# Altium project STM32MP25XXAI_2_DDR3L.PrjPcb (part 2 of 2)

## Sheet 2_DDR3L_16bits.SchDoc: 2_DDR3L_16bits
size A3; Date: Not used; ApprovedBy: Not used; CheckedBy: Not used; Author: Not used; CompanyName: STMicroelectronics; DrawnBy: Not used; Engineer: Not used; Organization: Not used; Address1: Not used; Address2: Not used; Address3: Not used; Address4: Not used; DocumentNumber: 6; Revision: Not used; SheetNumber: 6; SheetTotal: 7
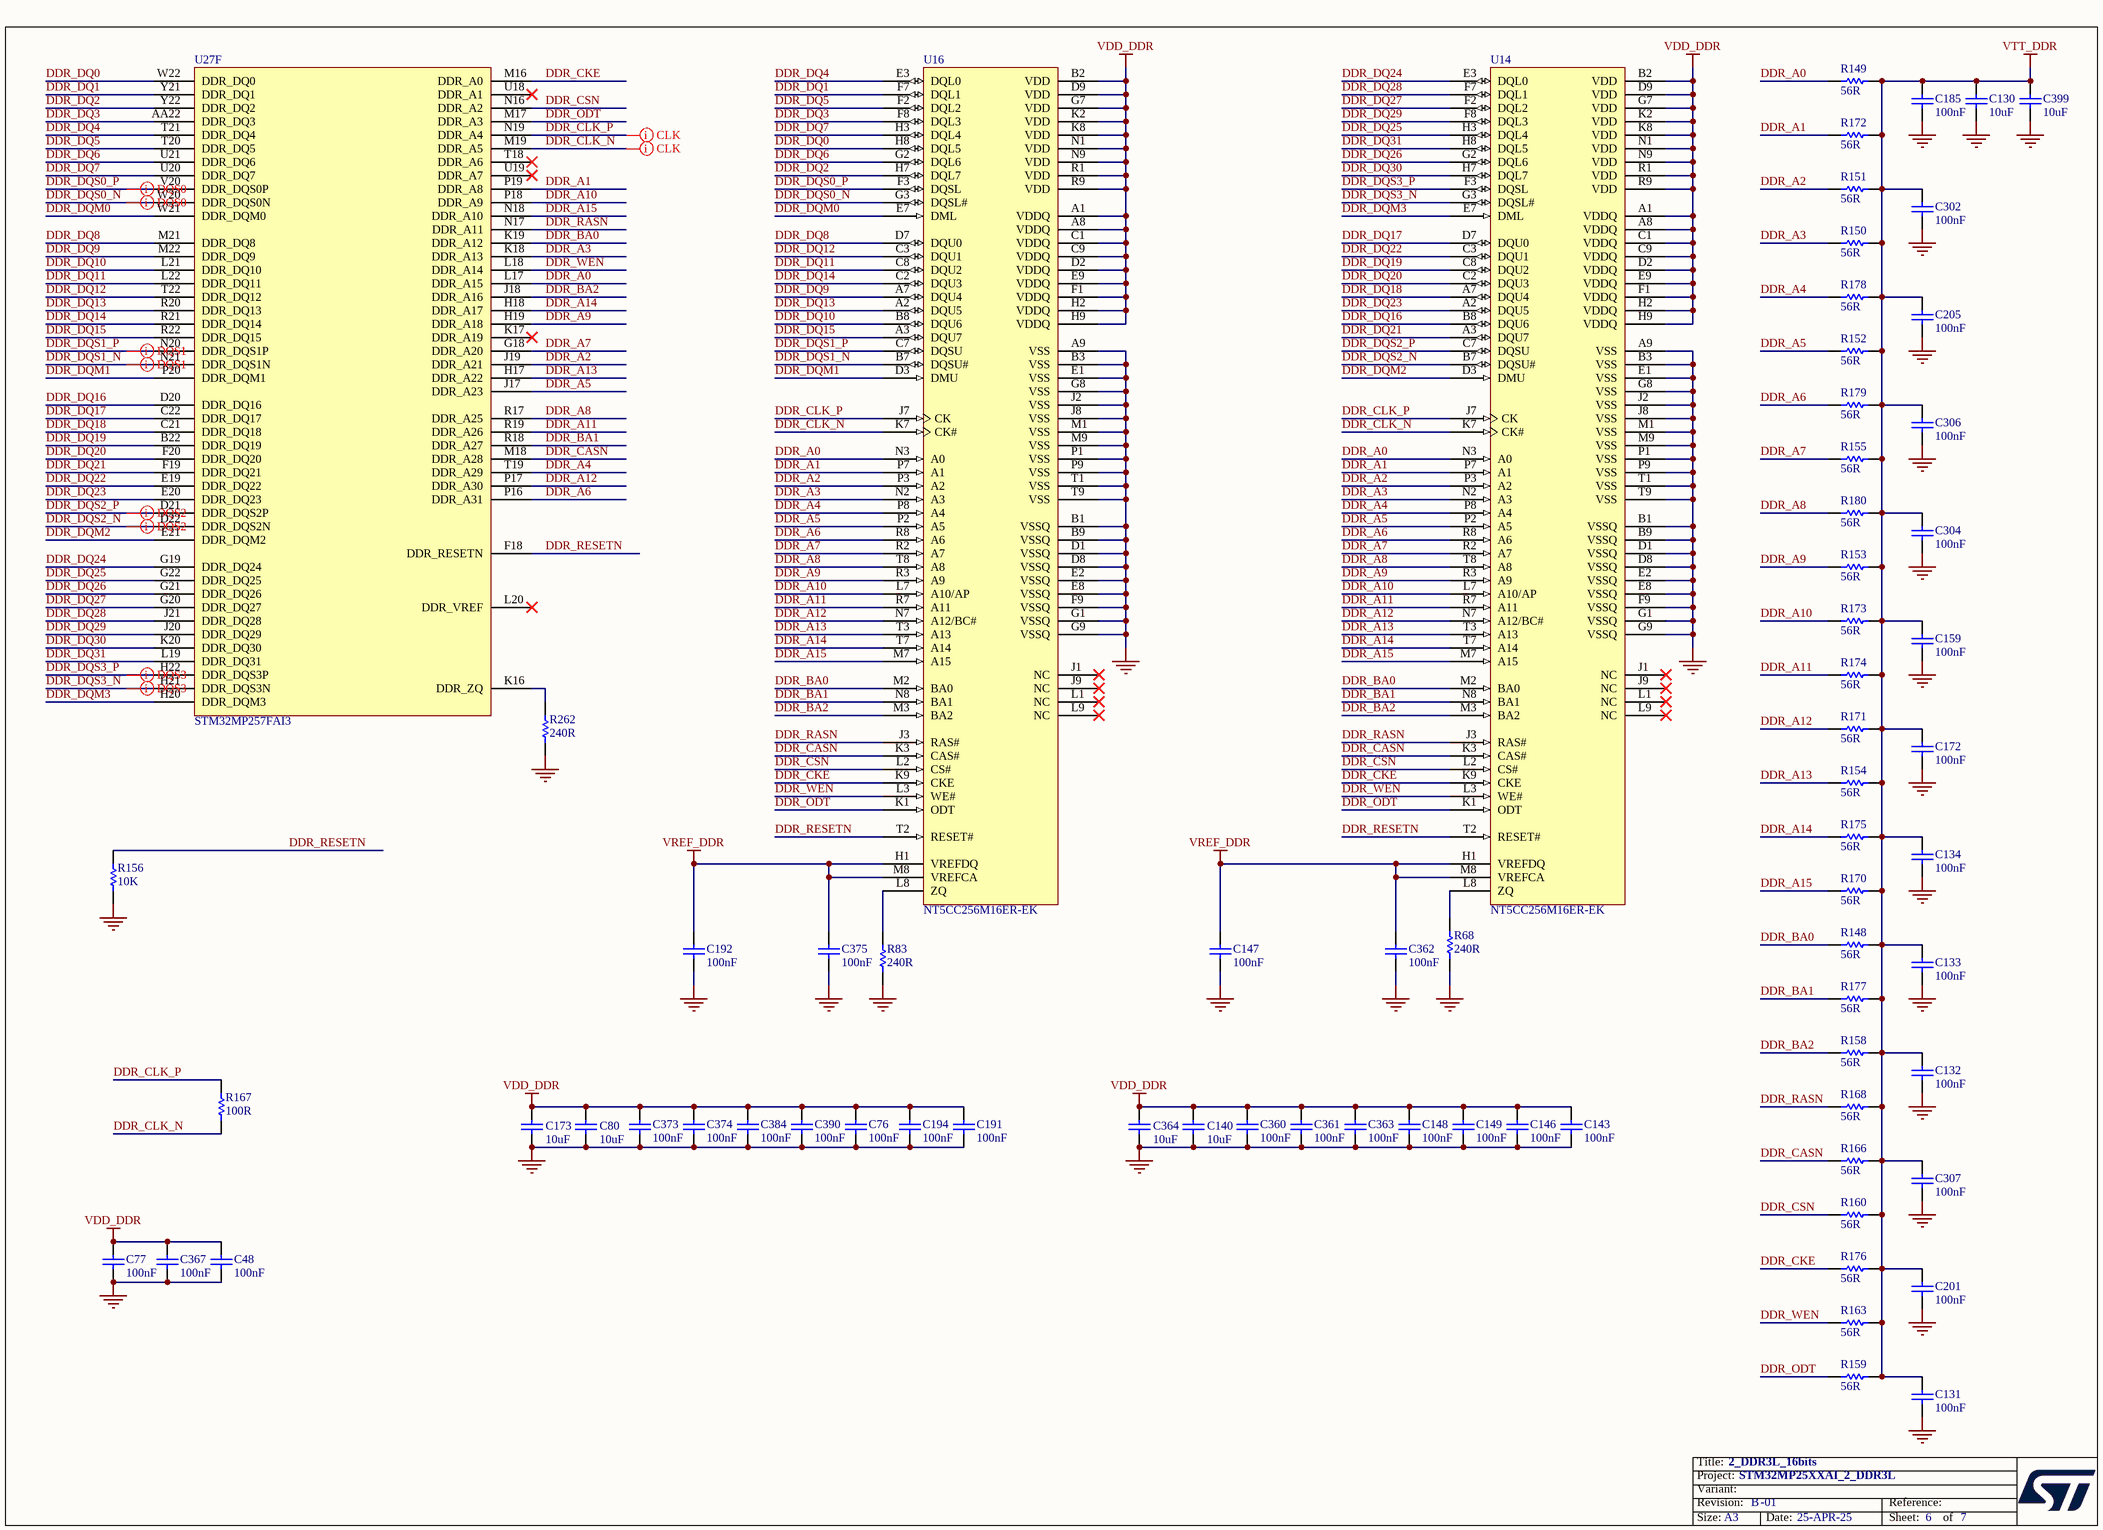
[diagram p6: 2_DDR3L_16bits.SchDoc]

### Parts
C48  value 100nF  [C0402]  (hidden comment: Capacitor)
C76  value 100nF  [C0402]  (hidden comment: Capacitor)
C77  value 100nF  [C0402]  (hidden comment: Capacitor)
C80  value 10uF  [C0603]  (hidden comment: Capacitor)
C130  value 10uF  [C0603]  (hidden comment: Capacitor)
C131  value 100nF  [C0402]  (hidden comment: Capacitor)
C132  value 100nF  [C0402]  (hidden comment: Capacitor)
C133  value 100nF  [C0402]  (hidden comment: Capacitor)
C134  value 100nF  [C0402]  (hidden comment: Capacitor)
C140  value 10uF  [C0603]  (hidden comment: Capacitor)
C143  value 100nF  [C0402]  (hidden comment: Capacitor)
C146  value 100nF  [C0402]  (hidden comment: Capacitor)
C147  value 100nF  [C0402]  (hidden comment: Capacitor)
C148  value 100nF  [C0402]  (hidden comment: Capacitor)
C149  value 100nF  [C0402]  (hidden comment: Capacitor)
C159  value 100nF  [C0402]  (hidden comment: Capacitor)
C172  value 100nF  [C0402]  (hidden comment: Capacitor)
C173  value 10uF  [C0603]  (hidden comment: Capacitor)
C185  value 100nF  [C0402]  (hidden comment: Capacitor)
C191  value 100nF  [C0402]  (hidden comment: Capacitor)
C192  value 100nF  [C0402]  (hidden comment: Capacitor)
C194  value 100nF  [C0402]  (hidden comment: Capacitor)
C201  value 100nF  [C0402]  (hidden comment: Capacitor)
C205  value 100nF  [C0402]  (hidden comment: Capacitor)
C302  value 100nF  [C0402]  (hidden comment: Capacitor)
C304  value 100nF  [C0402]  (hidden comment: Capacitor)
C306  value 100nF  [C0402]  (hidden comment: Capacitor)
C307  value 100nF  [C0402]  (hidden comment: Capacitor)
C360  value 100nF  [C0402]  (hidden comment: Capacitor)
C361  value 100nF  [C0402]  (hidden comment: Capacitor)
C362  value 100nF  [C0402]  (hidden comment: Capacitor)
C363  value 100nF  [C0402]  (hidden comment: Capacitor)
C364  value 10uF  [C0603]  (hidden comment: Capacitor)
C367  value 100nF  [C0402]  (hidden comment: Capacitor)
C373  value 100nF  [C0402]  (hidden comment: Capacitor)
C374  value 100nF  [C0402]  (hidden comment: Capacitor)
C375  value 100nF  [C0402]  (hidden comment: Capacitor)
C384  value 100nF  [C0402]  (hidden comment: Capacitor)
C390  value 100nF  [C0402]  (hidden comment: Capacitor)
C399  value 10uF  [C0603]  (hidden comment: Capacitor)
R68  value 240R  [R0402]  (hidden comment: Resistor)
R83  value 240R  [R0402]  (hidden comment: Resistor)
R148  value 56R  [R0402]  (hidden comment: Resistor)
R149  value 56R  [R0402]  (hidden comment: Resistor)
R150  value 56R  [R0402]  (hidden comment: Resistor)
R151  value 56R  [R0402]  (hidden comment: Resistor)
R152  value 56R  [R0402]  (hidden comment: Resistor)
R153  value 56R  [R0402]  (hidden comment: Resistor)
R154  value 56R  [R0402]  (hidden comment: Resistor)
R155  value 56R  [R0402]  (hidden comment: Resistor)
R156  value 10K  [R0402]  (hidden comment: Resistor)
R158  value 56R  [R0402]  (hidden comment: Resistor)
R159  value 56R  [R0402]  (hidden comment: Resistor)
R160  value 56R  [R0402]  (hidden comment: Resistor)
R163  value 56R  [R0402]  (hidden comment: Resistor)
R166  value 56R  [R0402]  (hidden comment: Resistor)
R167  value 100R  [R0402]  (hidden comment: Resistor)
R168  value 56R  [R0402]  (hidden comment: Resistor)
R170  value 56R  [R0402]  (hidden comment: Resistor)
R171  value 56R  [R0402]  (hidden comment: Resistor)
R172  value 56R  [R0402]  (hidden comment: Resistor)
R173  value 56R  [R0402]  (hidden comment: Resistor)
R174  value 56R  [R0402]  (hidden comment: Resistor)
R175  value 56R  [R0402]  (hidden comment: Resistor)
R176  value 56R  [R0402]  (hidden comment: Resistor)
R177  value 56R  [R0402]  (hidden comment: Resistor)
R178  value 56R  [R0402]  (hidden comment: Resistor)
R179  value 56R  [R0402]  (hidden comment: Resistor)
R180  value 56R  [R0402]  (hidden comment: Resistor)
R262  value 240R  [R0201_H0P23]  (hidden comment: Resistor)
U14  NT5CC256M16ER-EK  [ICC_VFBGA96_9x13_P080]
U16  NT5CC256M16ER-EK  [ICC_VFBGA96_9x13_P080]
U27  STM32MP257FAI3  [ICC_LFBGA436_18X18_P080_H1P70_STM32MP257_CODE-B0D1]  (part F of 9)

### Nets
GND: C48.1 C76.1 C77.1 C80.1 C130.1 C131.1 C132.1 C133.1 C134.1 C140.1 C143.1 C146.1 C147.1 C148.1 C149.1 C159.1 C172.1 C173.1 C185.1 C191.1 C192.1 C194.1 C201.1 C205.1 C302.1 C304.1 C306.1 C307.1 C360.1 C361.1 C362.1 C363.1 C364.1 C367.1 C373.1 C374.1 C375.1 C384.1 C390.1 C399.1 R68.1 R83.1 R156.1 R262.1 U14.A9(VSS) U14.B1(VSSQ) U14.B3(VSS) U14.B9(VSSQ) U14.D1(VSSQ) U14.D8(VSSQ) U14.E1(VSS) U14.E2(VSSQ) U14.E8(VSSQ) U14.F9(VSSQ) U14.G1(VSSQ) U14.G8(VSS) U14.G9(VSSQ) U14.J2(VSS) U14.J8(VSS) U14.M1(VSS) U14.M9(VSS) U14.P1(VSS) U14.P9(VSS) U14.T1(VSS) U14.T9(VSS) U16.A9(VSS) U16.B1(VSSQ) U16.B3(VSS) U16.B9(VSSQ) U16.D1(VSSQ) U16.D8(VSSQ) U16.E1(VSS) U16.E2(VSSQ) U16.E8(VSSQ) U16.F9(VSSQ) U16.G1(VSSQ) U16.G8(VSS) U16.G9(VSSQ) U16.J2(VSS) U16.J8(VSS) U16.M1(VSS) U16.M9(VSS) U16.P1(VSS) U16.P9(VSS) U16.T1(VSS) U16.T9(VSS)
VDD_DDR: C48.2 C76.2 C77.2 C80.2 C140.2 C143.2 C146.2 C148.2 C149.2 C173.2 C191.2 C194.2 C360.2 C361.2 C363.2 C364.2 C367.2 C373.2 C374.2 C384.2 C390.2 U14.A1(VDDQ) U14.A8(VDDQ) U14.B2(VDD) U14.C1(VDDQ) U14.C9(VDDQ) U14.D2(VDDQ) U14.D9(VDD) U14.E9(VDDQ) U14.F1(VDDQ) U14.G7(VDD) U14.H2(VDDQ) U14.H9(VDDQ) U14.K2(VDD) U14.K8(VDD) U14.N1(VDD) U14.N9(VDD) U14.R1(VDD) U14.R9(VDD) U16.A1(VDDQ) U16.A8(VDDQ) U16.B2(VDD) U16.C1(VDDQ) U16.C9(VDDQ) U16.D2(VDDQ) U16.D9(VDD) U16.E9(VDDQ) U16.F1(VDDQ) U16.G7(VDD) U16.H2(VDDQ) U16.H9(VDDQ) U16.K2(VDD) U16.K8(VDD) U16.N1(VDD) U16.N9(VDD) U16.R1(VDD) U16.R9(VDD)
VREF_DDR: C147.2 C192.2 C362.2 C375.2 U14.H1(VREFDQ) U14.M8(VREFCA) U16.H1(VREFDQ) U16.M8(VREFCA)
VTT_DDR: C130.2 C131.2 C132.2 C133.2 C134.2 C159.2 C172.2 C185.2 C201.2 C205.2 C302.2 C304.2 C306.2 C307.2 C399.2 R148.2 R149.2 R150.2 R151.2 R152.2 R153.2 R154.2 R155.2 R158.2 R159.2 R160.2 R163.2 R166.2 R168.2 R170.2 R171.2 R172.2 R173.2 R174.2 R175.2 R176.2 R177.2 R178.2 R179.2 R180.2
DDR_A0: R149.1 U14.N3(A0) U16.N3(A0) U27.L17(DDR_A15)
DDR_A1: R172.1 U14.P7(A1) U16.P7(A1) U27.P19(DDR_A8)
DDR_A2: R151.1 U14.P3(A2) U16.P3(A2) U27.J19(DDR_A21)
DDR_A3: R150.1 U14.N2(A3) U16.N2(A3) U27.K18(DDR_A13)
DDR_A4: R178.1 U14.P8(A4) U16.P8(A4) U27.T19(DDR_A29)
DDR_A5: R152.1 U14.P2(A5) U16.P2(A5) U27.J17(DDR_A23)
DDR_A6: R179.1 U14.R8(A6) U16.R8(A6) U27.P16(DDR_A31)
DDR_A7: R155.1 U14.R2(A7) U16.R2(A7) U27.G18(DDR_A20)
DDR_A8: R180.1 U14.T8(A8) U16.T8(A8) U27.R17(DDR_A25)
DDR_A9: R153.1 U14.R3(A9) U16.R3(A9) U27.H19(DDR_A18)
DDR_A10: R173.1 U14.L7(A10/AP) U16.L7(A10/AP) U27.P18(DDR_A9)
DDR_A11: R174.1 U14.R7(A11) U16.R7(A11) U27.R19(DDR_A26)
DDR_A12: R171.1 U14.N7(A12/BC#) U16.N7(A12/BC#) U27.P17(DDR_A30)
DDR_A13: R154.1 U14.T3(A13) U16.T3(A13) U27.H17(DDR_A22)
DDR_A14: R175.1 U14.T7(A14) U16.T7(A14) U27.H18(DDR_A17)
DDR_A15: R170.1 U14.M7(A15) U16.M7(A15) U27.N18(DDR_A10)
DDR_BA0: R148.1 U14.M2(BA0) U16.M2(BA0) U27.K19(DDR_A12)
DDR_BA1: R177.1 U14.N8(BA1) U16.N8(BA1) U27.R18(DDR_A27)
DDR_BA2: R158.1 U14.M3(BA2) U16.M3(BA2) U27.J18(DDR_A16)
DDR_CASN: R166.1 U14.K3(CAS#) U16.K3(CAS#) U27.M18(DDR_A28)
DDR_CKE: R176.1 U14.K9(CKE) U16.K9(CKE) U27.M16(DDR_A0)
DDR_CLK_N: R167.2 U14.K7(CK#) U16.K7(CK#) U27.M19(DDR_A5)
DDR_CLK_P: R167.1 U14.J7(CK) U16.J7(CK) U27.N19(DDR_A4)
DDR_CSN: R160.1 U14.L2(CS#) U16.L2(CS#) U27.N16(DDR_A2)
DDR_DQ0: U16.H8(DQL5) U27.W22(DDR_DQ0)
DDR_DQ1: U16.F7(DQL1) U27.Y21(DDR_DQ1)
DDR_DQ2: U16.H7(DQL7) U27.Y22(DDR_DQ2)
DDR_DQ3: U16.F8(DQL3) U27.AA22(DDR_DQ3)
DDR_DQ4: U16.E3(DQL0) U27.T21(DDR_DQ4)
DDR_DQ5: U16.F2(DQL2) U27.T20(DDR_DQ5)
DDR_DQ6: U16.G2(DQL6) U27.U21(DDR_DQ6)
DDR_DQ7: U16.H3(DQL4) U27.U20(DDR_DQ7)
DDR_DQ8: U16.D7(DQU0) U27.M21(DDR_DQ8)
DDR_DQ9: U16.A7(DQU4) U27.M22(DDR_DQ9)
DDR_DQ10: U16.B8(DQU6) U27.L21(DDR_DQ10)
DDR_DQ11: U16.C8(DQU2) U27.L22(DDR_DQ11)
DDR_DQ12: U16.C3(DQU1) U27.T22(DDR_DQ12)
DDR_DQ13: U16.A2(DQU5) U27.R20(DDR_DQ13)
DDR_DQ14: U16.C2(DQU3) U27.R21(DDR_DQ14)
DDR_DQ15: U16.A3(DQU7) U27.R22(DDR_DQ15)
DDR_DQ16: U14.B8(DQU6) U27.D20(DDR_DQ16)
DDR_DQ17: U14.D7(DQU0) U27.C22(DDR_DQ17)
DDR_DQ18: U14.A7(DQU4) U27.C21(DDR_DQ18)
DDR_DQ19: U14.C8(DQU2) U27.B22(DDR_DQ19)
DDR_DQ20: U14.C2(DQU3) U27.F20(DDR_DQ20)
DDR_DQ21: U14.A3(DQU7) U27.F19(DDR_DQ21)
DDR_DQ22: U14.C3(DQU1) U27.E19(DDR_DQ22)
DDR_DQ23: U14.A2(DQU5) U27.E20(DDR_DQ23)
DDR_DQ24: U14.E3(DQL0) U27.G19(DDR_DQ24)
DDR_DQ25: U14.H3(DQL4) U27.G22(DDR_DQ25)
DDR_DQ26: U14.G2(DQL6) U27.G21(DDR_DQ26)
DDR_DQ27: U14.F2(DQL2) U27.G20(DDR_DQ27)
DDR_DQ28: U14.F7(DQL1) U27.J21(DDR_DQ28)
DDR_DQ29: U14.F8(DQL3) U27.J20(DDR_DQ29)
DDR_DQ30: U14.H7(DQL7) U27.K20(DDR_DQ30)
DDR_DQ31: U14.H8(DQL5) U27.L19(DDR_DQ31)
DDR_DQM0: U16.E7(DML) U27.W21(DDR_DQM0)
DDR_DQM1: U16.D3(DMU) U27.P20(DDR_DQM1)
DDR_DQM2: U14.D3(DMU) U27.E21(DDR_DQM2)
DDR_DQM3: U14.E7(DML) U27.H20(DDR_DQM3)
DDR_DQS0_N: U16.G3(DQSL#) U27.W20(DDR_DQS0N)
DDR_DQS0_P: U16.F3(DQSL) U27.V20(DDR_DQS0P)
DDR_DQS1_N: U16.B7(DQSU#) U27.N21(DDR_DQS1N)
DDR_DQS1_P: U16.C7(DQSU) U27.N20(DDR_DQS1P)
DDR_DQS2_N: U14.B7(DQSU#) U27.D22(DDR_DQS2N)
DDR_DQS2_P: U14.C7(DQSU) U27.D21(DDR_DQS2P)
DDR_DQS3_N: U14.G3(DQSL#) U27.H21(DDR_DQS3N)
DDR_DQS3_P: U14.F3(DQSL) U27.H22(DDR_DQS3P)
DDR_ODT: R159.1 U14.K1(ODT) U16.K1(ODT) U27.M17(DDR_A3)
DDR_RASN: R168.1 U14.J3(RAS#) U16.J3(RAS#) U27.N17(DDR_A11)
DDR_RESETN: R156.2 U14.T2(RESET#) U16.T2(RESET#) U27.F18(DDR_RESETN)
DDR_WEN: R163.1 U14.L3(WE#) U16.L3(WE#) U27.L18(DDR_A14)
NetR68_2: R68.2 U14.L8(ZQ)
NetR83_2: R83.2 U16.L8(ZQ)
NetR262_2: R262.2 U27.K16(DDR_ZQ)

Not connected (* = marked no-connect by the designer): U14 J1(NC)* J9(NC)* L1(NC)* L9(NC)*; U16 J1(NC)* J9(NC)* L1(NC)* L9(NC)*; U27 K17(DDR_A19)* L20(DDR_VREF)* T18(DDR_A6)* U18(DDR_A1)* U19(DDR_A7)*

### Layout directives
differential pair: DDR_CLK_N, DDR_CLK_P, DDR_DQS0_N, DDR_DQS0_P, DDR_DQS1_N, DDR_DQS1_P, DDR_DQS2_N, DDR_DQS2_P, DDR_DQS3_N, DDR_DQS3_P

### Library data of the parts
C48 C76 C77 C131-C134 C143 C146-C149 C159 C172 C185 C191 C192 C194 C201 C205 C302 C304 C306 C307 C360-C363 C367 C373-C375 C384 C390 = MCD-00006: Capacitor, MLCC, 100nF, 16V, X7R, +/-10%, 0402, T=0.5mm; Part_Preference: Recommended; Manufacturer: YAGEO; Manufacturer_Part_Number: CC0402KRX7R7BB104; Alternate_Manufacturer: MURATA; Alternate_Manufacturer_Part_Number: GCM155R71C104KA55D; Partial_Alternate_Internal_Part_Number: MCD-03299; Order_Code_RS: 9402047; Component_Country_Of_Origin: China; ID: 2474; ShowFields: YES
C80 C140 C173 C364 = MCD-00099: Capacitor, MLCC, 10uF, 10V, X5R, +/-10%, 0603, T=0.8mm; Manufacturer_Part_Number: GRM188R61A106KE69D; Manufacturer: MURATA; Part_Preference: Recommended; Partial_Alternate_Internal_Part_Number: MCD-03152; Order_Code_RS: 2494233; Component_Country_Of_Origin: Japan°°; ID: 2770; ShowFields: YES
C130 C399 = MCD-00099: Capacitor, MLCC, 10uF, 10V, X5R, +/-10%, 0603, T=0.8mm; Part_Preference: Recommended; Manufacturer: MURATA; Manufacturer_Part_Number: GRM188R61A106KE69D; Partial_Alternate_Internal_Part_Number: MCD-03152; Order_Code_RS: 2494233; Component_Country_Of_Origin: Japan°°; ShowFields: YES; ID: 2770
R68 R83 = MCD-00120: Resistor,240R,0402,1%,1/16W; Part_Preference: Recommended; Manufacturer: YAGEO; Manufacturer_Part_Number: RC0402FR-07240RL; Component_Country_Of_Origin: China; ID: 2745; ShowFields: YES
R148-R155 R158-R160 R163 R166 R168 R170-R180 = MCD-00054: Resistor, 56R, 0402, +/-1%, 1/16W; Part_Preference: Recommended; Manufacturer: YAGEO; Manufacturer_Part_Number: RC0402FR-0756RL; Order_Code_RS: 9239081; Component_Country_Of_Origin: China; ID: 2538; ShowFields: YES
R156 = MCD-00053: Resistor,10K,0402,1%,1/16W; BMS_Part_Number: 9131590; Part_Preference: Recommended; Manufacturer: YAGEO; Manufacturer_Part_Number: RC0402FR-0710KL; Order_Code_RS: 9239359; Component_Country_Of_Origin: China; ID: 2539; ShowFields: YES
R167 = MCD-01819: Resistor,100R,0402,0,5%,1/16W,±100ppm/°C; Part_Preference: Recommended; Manufacturer: YAGEO; Manufacturer_Part_Number: RC0402DR-07100RL; Component_Country_Of_Origin: China; ID: 3919; ShowFields: YES
R262 = MCD-02253: Resistor,240R,0201,1%,1/20W; Part_Preference: Recommended; Manufacturer: YAGEO; Manufacturer_Part_Number: RC0201FR-07240RL; Component_Country_Of_Origin: China; ID: 4353; ShowFields: YES
U14 U16 = MCD-01811: Memory,DDR3L,4Gb,256Mbx16,933Mhz,1V35,TFBGA; BMS_Part_Number: 9171435; Part_Type: IC; Part_Preference: Recommended; Manufacturer: NANYA; Component_Country_Of_Origin: Taiwan; ID: 3911; ShowFields: YES
U27 = MCD-02000: MPU, ARM Cortex-A35 + M33 32-bit MPU, 808KB RAM, With Crypto; Part_Type: IC; Part_Preference: Recommended; Manufacturer: STMICROELECTRONICS; Manufacturer_HQ_COO: EU; Component_Country_Of_Origin: Unknown; ShowFields: YES; ID: 4100

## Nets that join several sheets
1V8: PMIC (5 pins), STM32MP25XXAI Power (20 pins), eMMC (11 pins)
GND: STM32MP25XXAI I_Os (7 pins), PMIC (62 pins), STM32MP25XXAI Power (104 pins), eMMC (17 pins), 2_DDR3L_16bits (86 pins)
VDD3V3_USB: PMIC (C156.2 U26.13), STM32MP25XXAI Power (R286.1)
VDD_DDR: PMIC (7 pins), STM32MP25XXAI Power (16 pins), 2_DDR3L_16bits (57 pins)
VDD_EMMC: PMIC (C190.1 U26.16), eMMC (6 pins)
VDDA1V8_AON: STM32MP25XXAI I_Os (U27.T7), PMIC (C189.2 U26.14), STM32MP25XXAI Power (C234.2 U27.R7)
VDDCORE: PMIC (6 pins), STM32MP25XXAI Power (20 pins)
VDDCPU: PMIC (5 pins), STM32MP25XXAI Power (14 pins)
VDDGPU: PMIC (6 pins), STM32MP25XXAI Power (12 pins)
VDDIO: STM32MP25XXAI I_Os (R27.2 R260.2 R261.2), PMIC (6 pins), STM32MP25XXAI Power (18 pins)
VDDIO_SDCARD: PMIC (C217.1 U26.2), STM32MP25XXAI Power (C71.2 U27.G10)
VREF_DDR: PMIC (C43.2 U26.45), 2_DDR3L_16bits (8 pins)
VTT_DDR: PMIC (C40.2 U26.44), 2_DDR3L_16bits (40 pins)
eMMC.SDMMC2_CK: STM32MP25XXAI I_Os (U27.A20), eMMC (R49.1 U24.M6)
eMMC.SDMMC2_CMD: STM32MP25XXAI I_Os (U27.F17), eMMC (R37.1 U24.M5)
eMMC.SDMMC2_D0: STM32MP25XXAI I_Os (U27.B19), eMMC (R44.1 U24.A3)
eMMC.SDMMC2_D1: STM32MP25XXAI I_Os (U27.E17), eMMC (U24.A4)
eMMC.SDMMC2_D2: STM32MP25XXAI I_Os (U27.C18), eMMC (U24.A5)
eMMC.SDMMC2_D3: STM32MP25XXAI I_Os (U27.C19), eMMC (U24.B2)
eMMC.SDMMC2_D4: STM32MP25XXAI I_Os (U27.A19), eMMC (U24.B3)
eMMC.SDMMC2_D5: STM32MP25XXAI I_Os (U27.D18), eMMC (U24.B4)
eMMC.SDMMC2_D6: STM32MP25XXAI I_Os (U27.E16), eMMC (U24.B5)
eMMC.SDMMC2_D7: STM32MP25XXAI I_Os (U27.D17), eMMC (U24.B6)
I2C7.SCL: STM32MP25XXAI I_Os (R261.1 U27.F16), PMIC (U26.33)
I2C7.SDA: STM32MP25XXAI I_Os (R260.1 U27.G15), PMIC (U26.34)
MP257_WAKEUP: STM32MP25XXAI I_Os (U27.Y2), PMIC (U26.32)
NRST: STM32MP25XXAI I_Os (C33.2 U27.U3), PMIC (R81.1)
NRSTC1MS: STM32MP25XXAI I_Os (R27.1 R272.1 U27.T3), PMIC (R59.1), eMMC (D5.2)
PMIC_WAKEUPn: STM32MP25XXAI I_Os (U27.P6), PMIC (R46.1)
PWR_CPU_ON: STM32MP25XXAI I_Os (R272.2 U27.T6), PMIC (R60.1)
PWR_ON: STM32MP25XXAI I_Os (U27.T5), PMIC (R2.1)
